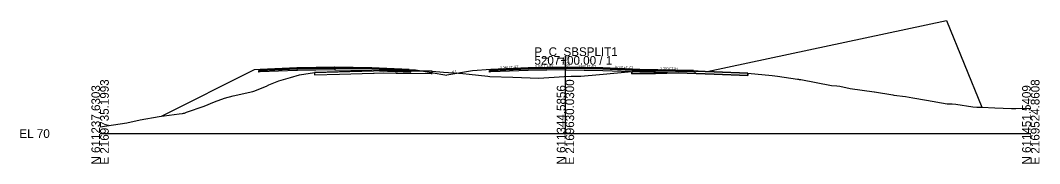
# Model space of a CAD drawing. Extents: x -26 to 1303, y -3010 to 12033.
# Drawn here: x 974.3 to 1302.8, y 5490.3 to 5536.5 of the extents above; entities that cross this region are included whole.
import ezdxf

# ---------------------------------------------------------------- set-up
doc = ezdxf.new("R2010")
doc.units = 0
for name, color, linetype in [('RD_GPK_XS_Cell', 7, 'Continuous'), ('RD_Sketch10', 7, 'Continuous'), ('RD_XS_Base', 7, 'Continuous'), ('RD_XS_ExGround', 7, 'Continuous'), ('RD_XS_ExPaveRet', 7, 'Continuous'), ('RD_XS_Greenside', 7, 'Continuous'), ('RD_XS_Pave', 7, 'Continuous'), ('RD_XS_PaveOvlay_CP', 7, 'Continuous'), ('RD_XS_TieSlope', 7, 'Continuous'), ('RD_XS_TX_Elev_EX', 7, 'Continuous'), ('RD_XS_TX_Elev_PR', 7, 'Continuous'), ('RD_XS_TX_Slope', 7, 'Continuous')]:
    doc.layers.add(name, color=color, linetype=linetype)

msp = doc.modelspace()

# ---------------------------------------------------------------- linework, layer by layer
at = {"layer": 'RD_GPK_XS_Cell'}
for p, q in [((1150, 5500), (1150, 5525)), ((1000, 5500), (1150, 5500)), ((1150, 5500), (1300, 5500))]:
    msp.add_line(p, q, dxfattribs=at)
at = {"layer": 'RD_Sketch10'}
msp.add_lwpolyline([(1195.64, 5519.98), (1272.79, 5536.5), (1284.17, 5508.5)], dxfattribs=at)
at = {"layer": 'RD_XS_Base'}
for p, q in [((1051.13, 5520.34), (1051.61, 5520.36)), ((1051.13, 5520.33), (1051.13, 5520.34)), ((1051.13, 5519.84), (1051.13, 5520.33)), ((1051.61, 5519.86), (1051.13, 5519.84)), ((1051.61, 5520.36), (1051.63, 5520.36)), ((1051.63, 5519.86), (1051.61, 5519.86)), ((1051.63, 5520.36), (1063.45, 5520.83)), ((1063.45, 5520.33), (1051.63, 5519.86)), ((1063.45, 5520.83), (1063.63, 5520.84)), ((1063.63, 5520.34), (1063.45, 5520.33)), ((1063.63, 5520.84), (1075.61, 5521.08)), ((1075.61, 5520.58), (1063.63, 5520.34)), ((1075.61, 5521.08), (1075.63, 5521.08)), ((1075.63, 5520.58), (1075.61, 5520.58)), ((1075.63, 5521.08), (1075.63, 5521.24)), ((1075.63, 5521.24), (1075.63, 5521.24)), ((1075.63, 5521.24), (1075.63, 5521.24)), ((1075.63, 5521.24), (1075.63, 5520.58)), ((1075.63, 5521.08), (1075.63, 5521.24)), ((1075.63, 5521.24), (1075.63, 5520.58)), ((1075.63, 5521.08), (1075.63, 5521.08)), ((1075.63, 5521.08), (1075.63, 5520.58)), ((1075.67, 5521.08), (1075.63, 5521.08)), ((1075.63, 5521.08), (1075.63, 5520.58)), ((1087.63, 5520.84), (1075.63, 5521.08)), ((1075.63, 5521.08), (1075.63, 5521.08)), ((1075.63, 5520.58), (1075.67, 5520.58)), ((1075.63, 5520.58), (1075.63, 5520.58)), ((1075.63, 5520.58), (1075.63, 5520.58)), ((1075.63, 5520.58), (1087.63, 5520.34)), ((1099.63, 5520.36), (1087.63, 5520.84)), ((1087.63, 5520.34), (1100.13, 5519.84)), ((1089.63, 5520.76), (1089.63, 5520.76)), ((1089.63, 5520.26), (1089.63, 5520.26)), ((1100.13, 5520.34), (1099.63, 5520.36)), ((1099.63, 5520.36), (1099.63, 5520.36)), ((1100.13, 5519.84), (1100.13, 5520.34)), ((1100.13, 5520.34), (1100.13, 5520.34)), ((1100.13, 5519.84), (1100.13, 5519.84)), ((1100.13, 5519.84), (1100.13, 5519.84)), ((1125.5, 5520.34), (1126, 5520.36)), ((1125.5, 5519.84), (1125.5, 5520.34)), ((1125.5, 5520.34), (1125.5, 5520.34)), ((1126, 5519.86), (1125.5, 5519.84)), ((1125.5, 5519.84), (1125.5, 5519.84)), ((1125.5, 5519.84), (1125.5, 5519.84)), ((1126, 5520.36), (1138, 5520.84)), ((1126, 5520.36), (1126, 5520.36)), ((1138, 5520.34), (1126, 5519.86)), ((1126, 5519.86), (1126, 5519.86)), ((1136, 5520.76), (1136, 5520.76)), ((1136, 5520.26), (1136, 5520.26)), ((1138, 5520.84), (1150, 5521.08)), ((1150, 5520.58), (1138, 5520.34)), ((1150, 5521.08), (1150, 5521.24)), ((1150, 5521.24), (1150, 5520.58)), ((1150, 5521.08), (1150, 5520.58)), ((1150, 5521.08), (1150, 5521.08)), ((1162, 5520.84), (1150, 5521.08)), ((1150, 5521.08), (1150, 5521.08)), ((1150, 5520.58), (1150, 5520.58)), ((1150, 5520.58), (1150, 5520.58)), ((1150, 5520.58), (1162, 5520.34)), ((1174, 5520.36), (1162, 5520.84)), ((1162, 5520.84), (1162, 5520.84)), ((1162, 5520.34), (1162, 5520.34)), ((1162, 5520.34), (1174, 5519.86)), ((1191.3, 5520.01), (1174, 5520.36)), ((1174, 5520.36), (1174, 5520.36)), ((1174, 5519.86), (1174, 5519.86)), ((1174, 5519.86), (1191.8, 5519.5)), ((1191.8, 5520), (1191.3, 5520.01)), ((1191.3, 5520.01), (1191.3, 5520.01)), ((1191.8, 5519.5), (1191.8, 5520)), ((1191.8, 5520), (1191.8, 5520)), ((1191.8, 5519.5), (1191.8, 5519.5)), ((1191.8, 5519.5), (1191.8, 5519.5))]:
    msp.add_line(p, q, dxfattribs=at)
at = {"layer": 'RD_XS_ExGround'}
msp.add_lwpolyline([(1000, 5502.12), (1008.67, 5503.47), (1012.89, 5504.43), (1019.03, 5505.46), (1025.52, 5506.34), (1026.61, 5506.48), (1026.84, 5506.54), (1027.21, 5506.61), (1027.87, 5506.86), (1033.55, 5508.81), (1036.88, 5510.23), (1040.06, 5511.44), (1042.88, 5512.13), (1049.26, 5513.57), (1049.59, 5513.65), (1053.62, 5515.32), (1054.42, 5515.66), (1057.63, 5517), (1061.38, 5518.09), (1064.24, 5518.95), (1069.1, 5519.67), (1088.16, 5520.23), (1091.47, 5520.33), (1095.89, 5520.27), (1107.01, 5520.13), (1110.67, 5519.84), (1115.55, 5519.5), (1116.9, 5519.32), (1119, 5519.15), (1124.96, 5518.5), (1125.65, 5518.4), (1132.99, 5518.15), (1141.4, 5517.89), (1149.54, 5518.37), (1151.87, 5518.5), (1152.64, 5518.52), (1154.97, 5518.55), (1160.99, 5519.04), (1171.36, 5519.99), (1179.06, 5520.15), (1186.33, 5520.32), (1197.89, 5519.9), (1208.77, 5519.5), (1216.58, 5518.67), (1218.39, 5518.5), (1224.85, 5517.56), (1225.16, 5517.52), (1225.38, 5517.48), (1225.84, 5517.4), (1235.79, 5515.5), (1237.47, 5515.39), (1238.43, 5515.24), (1241.76, 5514.54), (1249.54, 5513.46), (1249.62, 5513.44), (1255.49, 5512.45), (1255.84, 5512.4), (1259.56, 5511.96), (1262.01, 5511.5), (1266.4, 5510.78), (1273.03, 5509.63), (1274.63, 5509.56), (1275.8, 5509.53), (1281.35, 5508.62), (1282.65, 5508.49), (1284.17, 5508.5), (1288.39, 5508.32), (1293.77, 5508.11), (1294.73, 5508.06), (1295.19, 5508.06), (1300, 5508.2)], dxfattribs=at)
at = {"layer": 'RD_XS_ExPaveRet'}
for points in [[(1069.1, 5519.67), (1069.1, 5519.35), (1069.1, 5518.92), (1077.21, 5519.16), (1088.16, 5519.48), (1088.38, 5519.49), (1091.47, 5519.58), (1095.41, 5519.52), (1095.89, 5519.52), (1106.76, 5519.38), (1107.01, 5519.38), (1107.01, 5519.38), (1107.01, 5519.38), (1107.01, 5519.43), (1107.01, 5520.13), (1107.01, 5520.13), (1107.01, 5520.13), (1106.76, 5520.13), (1095.89, 5520.27), (1095.41, 5520.27), (1091.47, 5520.33), (1088.38, 5520.24), (1088.16, 5520.23), (1077.21, 5519.91), (1069.1, 5519.67)], [(1069.1, 5519.67), (1069.1, 5519.35), (1069.1, 5518.92), (1077.21, 5519.16), (1088.16, 5519.48), (1088.38, 5519.49), (1091.47, 5519.58), (1095.41, 5519.52), (1095.89, 5519.52), (1106.76, 5519.38), (1107.01, 5519.38), (1107.01, 5519.38), (1107.01, 5519.43), (1107.01, 5520.13), (1107.01, 5520.13), (1106.76, 5520.13), (1095.89, 5520.27), (1095.41, 5520.27), (1091.47, 5520.33), (1088.38, 5520.24), (1088.16, 5520.23), (1077.21, 5519.91), (1069.1, 5519.67)], [(1208.77, 5519.5), (1208.77, 5518.75), (1208.77, 5518.75), (1197.89, 5519.15), (1197.89, 5519.15), (1186.33, 5519.57), (1186.33, 5519.57), (1186.33, 5519.57), (1179.06, 5519.4), (1179.06, 5519.4), (1171.36, 5519.24), (1171.36, 5519.24), (1171.36, 5519.99), (1179.06, 5520.15), (1179.06, 5520.15), (1186.33, 5520.32), (1186.33, 5520.32), (1186.33, 5520.32), (1197.89, 5519.9), (1197.89, 5519.9), (1208.77, 5519.5)], [(1197.89, 5519.9), (1186.33, 5520.32), (1179.06, 5520.15), (1171.36, 5519.99), (1171.36, 5519.24), (1179.06, 5519.4), (1186.33, 5519.57), (1197.89, 5519.15), (1208.77, 5518.75), (1208.77, 5519.5), (1197.89, 5519.9)]]:
    msp.add_lwpolyline(points, dxfattribs=at)
at = {"layer": 'RD_XS_Greenside'}
for p, q in [((1049.63, 5520.52), (1019.64, 5505.53)), ((1101.63, 5520.52), (1111.77, 5518.83)), ((1120, 5520.2), (1111.77, 5518.83))]:
    msp.add_line(p, q, dxfattribs=at)
at = {"layer": 'RD_XS_Pave'}
for p, q in [((1063.45, 5521.15), (1051.63, 5520.68)), ((1063.45, 5520.99), (1051.63, 5520.52)), ((1051.63, 5520.52), (1063.45, 5520.99)), ((1051.63, 5520.36), (1063.45, 5520.83)), ((1051.63, 5520.68), (1051.63, 5520.68)), ((1051.63, 5520.68), (1051.63, 5520.52)), ((1051.63, 5520.52), (1051.63, 5520.52)), ((1051.63, 5520.52), (1051.63, 5520.36)), ((1063.63, 5521.16), (1063.45, 5521.15)), ((1063.63, 5521), (1063.45, 5520.99)), ((1063.45, 5520.99), (1063.63, 5521)), ((1063.45, 5520.83), (1063.63, 5520.84)), ((1075.61, 5521.4), (1063.63, 5521.16)), ((1075.61, 5521.24), (1063.63, 5521)), ((1063.63, 5521), (1075.61, 5521.24)), ((1063.63, 5520.84), (1075.61, 5521.08)), ((1075.63, 5521.4), (1075.61, 5521.4)), ((1075.63, 5521.24), (1075.61, 5521.24)), ((1075.61, 5521.24), (1075.63, 5521.24)), ((1075.61, 5521.08), (1075.63, 5521.08)), ((1075.67, 5521.4), (1075.63, 5521.4)), ((1087.63, 5521.16), (1075.63, 5521.4)), ((1075.63, 5521.08), (1075.63, 5521.24)), ((1075.63, 5521.24), (1075.63, 5521.24)), ((1075.63, 5521.24), (1075.67, 5521.24)), ((1075.67, 5521.24), (1075.63, 5521.24)), ((1075.63, 5521.24), (1075.63, 5521.24)), ((1075.63, 5521.24), (1075.63, 5521.08)), ((1075.63, 5521.08), (1075.63, 5521.24)), ((1075.63, 5521.24), (1087.63, 5521)), ((1087.63, 5521), (1075.63, 5521.24)), ((1075.63, 5521.24), (1075.63, 5521.08)), ((1075.63, 5521.08), (1075.67, 5521.08)), ((1075.63, 5521.08), (1075.63, 5521.08)), ((1075.63, 5521.08), (1075.63, 5521.08)), ((1075.63, 5521.08), (1087.63, 5520.84)), ((1099.63, 5520.68), (1087.63, 5521.16)), ((1087.63, 5521), (1099.63, 5520.52)), ((1099.63, 5520.52), (1087.63, 5521)), ((1087.63, 5520.84), (1099.63, 5520.36)), ((1089.63, 5521.08), (1089.63, 5521.08)), ((1089.63, 5520.92), (1089.63, 5520.92)), ((1089.63, 5520.92), (1089.63, 5520.92)), ((1089.63, 5520.76), (1089.63, 5520.76)), ((1099.63, 5520.52), (1099.63, 5520.68)), ((1099.63, 5520.68), (1099.63, 5520.68)), ((1099.63, 5520.52), (1099.63, 5520.52)), ((1099.63, 5520.52), (1099.63, 5520.52)), ((1099.63, 5520.36), (1099.63, 5520.52)), ((1099.63, 5520.52), (1099.63, 5520.52)), ((1099.63, 5520.36), (1099.63, 5520.36)), ((1099.63, 5520.36), (1099.63, 5520.36)), ((1138, 5521.16), (1126, 5520.68)), ((1138, 5521), (1126, 5520.52)), ((1126, 5520.52), (1138, 5521)), ((1126, 5520.36), (1138, 5520.84)), ((1126, 5520.68), (1126, 5520.68)), ((1126, 5520.68), (1126, 5520.52)), ((1126, 5520.52), (1126, 5520.52)), ((1126, 5520.52), (1126, 5520.36)), ((1126, 5520.52), (1126, 5520.52)), ((1126, 5520.52), (1126, 5520.52)), ((1126, 5520.36), (1126, 5520.36)), ((1126, 5520.36), (1126, 5520.36)), ((1136, 5521.08), (1136, 5521.08)), ((1136, 5520.92), (1136, 5520.92)), ((1136, 5520.92), (1136, 5520.92)), ((1136, 5520.76), (1136, 5520.76)), ((1150, 5521.4), (1138, 5521.16)), ((1150, 5521.24), (1138, 5521)), ((1138, 5521), (1150, 5521.24)), ((1138, 5520.84), (1150, 5521.08)), ((1162, 5521.16), (1150, 5521.4)), ((1150, 5521.08), (1150, 5521.24)), ((1150, 5521.24), (1162, 5521)), ((1162, 5521), (1150, 5521.24)), ((1150, 5521.24), (1150, 5521.24)), ((1150, 5521.24), (1150, 5521.08)), ((1150, 5521.08), (1150, 5521.08)), ((1150, 5521.08), (1150, 5521.08)), ((1150, 5521.08), (1150, 5521.08)), ((1150, 5521.08), (1162, 5520.84)), ((1174, 5520.68), (1162, 5521.16)), ((1162, 5521.16), (1162, 5521.16)), ((1162, 5521), (1162, 5521)), ((1162, 5521), (1174, 5520.52)), ((1174, 5520.52), (1162, 5521)), ((1162, 5521), (1162, 5521)), ((1162, 5520.84), (1162, 5520.84)), ((1162, 5520.84), (1174, 5520.36)), ((1191.3, 5520.33), (1174, 5520.68)), ((1174, 5520.68), (1174, 5520.68)), ((1174, 5520.52), (1174, 5520.52)), ((1174, 5520.52), (1191.3, 5520.17)), ((1191.3, 5520.17), (1174, 5520.52)), ((1174, 5520.52), (1174, 5520.52)), ((1174, 5520.36), (1174, 5520.36)), ((1174, 5520.36), (1191.3, 5520.01)), ((1191.3, 5520.17), (1191.3, 5520.33)), ((1191.3, 5520.33), (1191.3, 5520.33)), ((1191.3, 5520.17), (1191.3, 5520.17)), ((1191.3, 5520.17), (1191.3, 5520.17)), ((1191.3, 5520.01), (1191.3, 5520.17)), ((1191.3, 5520.17), (1191.3, 5520.17)), ((1191.3, 5520.01), (1191.3, 5520.01)), ((1191.3, 5520.01), (1191.3, 5520.01))]:
    msp.add_line(p, q, dxfattribs=at)
at = {"layer": 'RD_XS_PaveOvlay_CP'}
for p, q in [((1051.63, 5520.68), (1063.63, 5521.16)), ((1063.63, 5521.16), (1075.63, 5521.4)), ((1075.63, 5521.4), (1087.63, 5521.16)), ((1087.63, 5521.16), (1099.63, 5520.68)), ((1138, 5521.16), (1126, 5520.68)), ((1126, 5520.68), (1126, 5520.68)), ((1136, 5521.08), (1136, 5521.08)), ((1150, 5521.4), (1138, 5521.16)), ((1162, 5521.16), (1150, 5521.4)), ((1174, 5520.68), (1162, 5521.16)), ((1162, 5521.16), (1162, 5521.16)), ((1191.3, 5520.33), (1174, 5520.68)), ((1174, 5520.68), (1174, 5520.68)), ((1191.3, 5520.33), (1191.3, 5520.33))]:
    msp.add_line(p, q, dxfattribs=at)
at = {"layer": 'RD_XS_TieSlope'}
for p, q in [((1051.63, 5520.68), (1049.63, 5520.52)), ((1099.63, 5520.68), (1101.63, 5520.52)), ((1126, 5520.68), (1120, 5520.2)), ((1191.3, 5520.33), (1195.64, 5519.98))]:
    msp.add_line(p, q, dxfattribs=at)

# ---------------------------------------------------------------- texts
at = {"layer": 'RD_GPK_XS_Cell'}
for s, p in [('P_C_SBSPLIT1', (1140, 5525)), ('5207+00.00 / 1', (1140, 5522.2)), ('EL 70', (974, 5498.6))]:
    msp.add_text(s, height=2.8, dxfattribs=at).set_placement(p)
for s, p in [('E 2169735.1993', (1002.8, 5490)), ('E 2169630.0300', (1152.8, 5490)), ('E 2169524.8608', (1302.8, 5490)), ('N 611237.6303', (1000, 5490)), ('N 611344.5856', (1150, 5490)), ('N 611451.5409', (1300, 5490))]:
    msp.add_text(s, height=2.8, rotation=90, dxfattribs=at).set_placement(p)
at = {"layer": 'RD_XS_TX_Elev_EX'}
msp.add_text('88.39', height=0.6, rotation=90, dxfattribs=at).set_placement((1149.6, 5522.1))
at = {"layer": 'RD_XS_TX_Elev_PR'}
msp.add_text('91.40', height=1, rotation=90, dxfattribs=at).set_placement((1151.25, 5521.64))
at = {"layer": 'RD_XS_TX_Slope'}
for s, rotation, p in [('6:1', 9.4642, (1113.57, 5519.54)), ('0.040 FT./FT.', 2.2906, (1128.93, 5520.89)), ('0.020 FT./FT.', 1.1458, (1140.27, 5521.37)), ('0.020 FT./FT.', 358.8542, (1153.94, 5521.42)), ('0.040 FT./FT.', 357.7094, (1165.94, 5521.1)), ('0.020 FT./FT.', 358.8542, (1180.59, 5520.65))]:
    msp.add_text(s, height=0.75, rotation=rotation, dxfattribs=at).set_placement(p)

doc.saveas('drawing.dxf')
